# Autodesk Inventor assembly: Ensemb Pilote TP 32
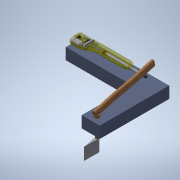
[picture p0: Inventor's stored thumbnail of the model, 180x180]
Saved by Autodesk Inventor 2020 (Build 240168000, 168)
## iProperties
Created: 2013-10
Part Number: Ensemb Pilote TP 32
Document SubType Name: Assembly
Designer: Bernard QUIVRIN
Author: Bernard QUIVRIN
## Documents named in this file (8)
- D:\Cours\Inventor salle SI\Pilote-inventor2012-TP32\Ensemb Pilote TP 32 SD.iam
- D:\Cours\Inventor salle SI\Pilote-inventor2012-TP32\banc.ipt
- D:\Cours\Inventor salle SI\Pilote-inventor2012-TP32\Ensemble_Safran_Barre.iam
- D:\Cours\Inventor salle SI\Pilote-inventor2012-TP32\Ensemble_Corps.iam
- D:\Cours\Inventor salle SI\Pilote-inventor2012-TP32\Ensemble_Axe_fixation.iam
- D:\Cours\Inventor salle SI\Pilote-inventor2012-TP32\Ensemble_Axe_moteur.iam
- D:\Cours\Inventor salle SI\Pilote-inventor2012-TP32\Ensemble_Vis_d'entraînement.iam
- D:\Cours\Inventor salle SI\Pilote-inventor2012-TP32\Ensemble_Tige.iam
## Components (7 placed, 7 different names)
1. banc:1 — Logement:1, Affleurement:1, Plaquage:1, Angle:1
2. Ensemble_Safran_Barre:1 [sub-assembly] — Logement:1, Plaquage:12
3. Ensemble_Corps:1 [sub-assembly] — Plaquage:3, Plaquage:4, Plaquage:5, Plaquage:6, Plaquage:7, Plaquage:8, Plaquage:9
4. Ensemble_Axe_fixation:1 [sub-assembly] — Affleurement:1, Plaquage:1, Plaquage:3, Plaquage:4
5. Ensemble_Axe_moteur:1 [sub-assembly] — Plaquage:5, Plaquage:6
6. Ensemble_Vis_d'entraînement:1 [sub-assembly] — Plaquage:7, Plaquage:8, Plaquage:10, Plaquage:11
7. Ensemble_Tige:1 [sub-assembly] — Plaquage:9, Plaquage:10, Plaquage:11, Angle:1, Plaquage:12
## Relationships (14: Mate 11, Insert 1, Flush 1, Angle 1)
- Logement:1 [Insert]: banc:1 ↔ Ensemble_Safran_Barre:1
- Affleurement:1 [Flush]: banc:1 ↔ Ensemble_Axe_fixation:1
- Plaquage:1 [Mate]: banc:1 ↔ Ensemble_Axe_fixation:1
- Plaquage:3 [Mate]: Ensemble_Corps:1 ↔ Ensemble_Axe_fixation:1
- Plaquage:4 [Mate]: Ensemble_Corps:1 ↔ Ensemble_Axe_fixation:1
- Plaquage:5 [Mate]: Ensemble_Corps:1 ↔ Ensemble_Axe_moteur:1
- Plaquage:6 [Mate]: Ensemble_Corps:1 ↔ Ensemble_Axe_moteur:1
- Plaquage:7 [Mate]: Ensemble_Corps:1 ↔ Ensemble_Vis_d'entraînement:1
- Plaquage:8 [Mate]: Ensemble_Corps:1 ↔ Ensemble_Vis_d'entraînement:1
- Plaquage:9 [Mate]: Ensemble_Corps:1 ↔ Ensemble_Tige:1
- Plaquage:10 [Mate]: Ensemble_Vis_d'entraînement:1 ↔ Ensemble_Tige:1
- Plaquage:11 [Mate]: Ensemble_Vis_d'entraînement:1 ↔ Ensemble_Tige:1
- Angle:1: banc:1 ↔ Ensemble_Tige:1
- Plaquage:12 [Mate]: Ensemble_Safran_Barre:1 ↔ Ensemble_Tige:1
